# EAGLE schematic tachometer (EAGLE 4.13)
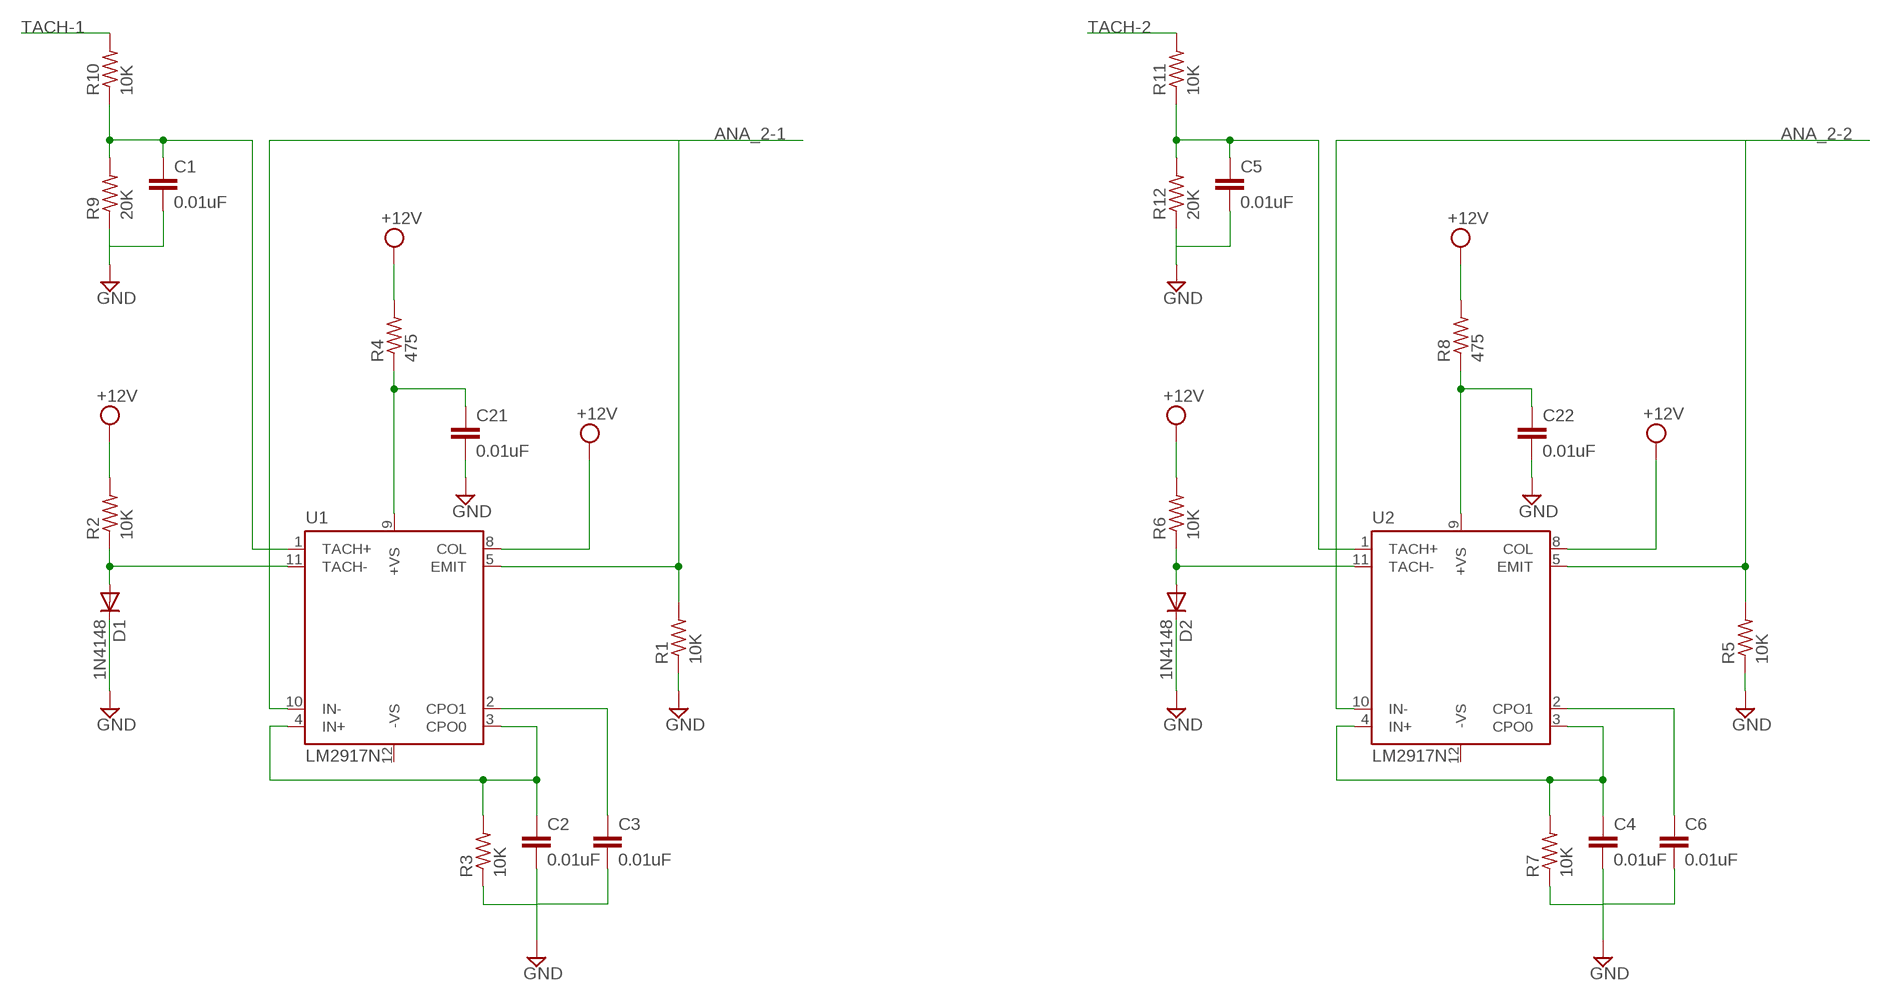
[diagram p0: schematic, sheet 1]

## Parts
C1  0.01uF  C-EU025_050-025X075  [C025_050-025X075]
C2  0.01uF  C-EU025_050-025X075  [C025_050-025X075]
C3  0.01uF  C-EU025_050-025X075  [C025_050-025X075]
C4  0.01uF  C-EU025_050-025X075  [C025_050-025X075]
C5  0.01uF  C-EU025_050-025X075  [C025_050-025X075]
C6  0.01uF  C-EU025_050-025X075  [C025_050-025X075]
C21  0.01uF  C-EU025_050-025X075  [C025_050-025X075]
C22  0.01uF  C-EU025_050-025X075  [C025_050-025X075]
D1  1N4148  [DO35-10]
D2  1N4148  [DO35-10]
R1  10K  R-US_0207/10  [0207/10]
R2  10K  R-US_0207/10  [0207/10]
R3  10K  R-US_0207/10  [0207/10]
R4  475  R-US_0207/10  [0207/10]
R5  10K  R-US_0207/10  [0207/10]
R6  10K  R-US_0207/10  [0207/10]
R7  10K  R-US_0207/10  [0207/10]
R8  475  R-US_0207/10  [0207/10]
R9  20K  R-US_0207/10  [0207/10]
R10  10K  R-US_0207/10  [0207/10]
R11  10K  R-US_0207/10  [0207/10]
R12  20K  R-US_0207/10  [0207/10]
U1  LM2917N  [DIL14]
U2  LM2917N  [DIL14]

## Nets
ANA_2-1: R1.2 U1.5(EMIT) U1.10(IN-)
ANA_2-2: R5.2 U2.5(EMIT) U2.10(IN-)
GND: C1.2 C2.2 C3.2 C4.2 C5.2 C6.2 C21.2 C22.2 D1.C D2.C R1.1 R3.1 R5.1 R7.1 R9.1 R12.1
N$1: D1.A R2.1 U1.11(TACH-)
N$2: C21.1 R4.1 U1.9(+VS)
N$3: C1.1 R9.2 R10.1 U1.1(TACH+)
N$4: C2.1 R3.2 U1.3(CPO0) U1.4(IN+)
N$5: D2.A R6.1 U2.11(TACH-)
N$6: C5.1 R11.1 R12.2 U2.1(TACH+)
N$7: C22.1 R8.1 U2.9(+VS)
N$8: C4.1 R7.2 U2.3(CPO0) U2.4(IN+)
N$9: C3.1 U1.2(CPO1)
N$10: C6.1 U2.2(CPO1)
TACH-1: R10.2
TACH-2: R11.2
VCC: R2.2 R4.2 R6.2 R8.2 U1.8(COL) U2.8(COL) ; supply symbol labelled +12V

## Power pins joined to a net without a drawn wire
-VS: U1.12(-VS) U2.12(-VS)

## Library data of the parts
C1-C6 C21 C22 = rcl:C-EU: CAPACITOR, European symbol
D1 D2 = diode:1N4148: DIODE
R1-R12 = rcl:R-US_: RESISTOR, American symbol
U1 U2 = analog-devices:LM2917N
